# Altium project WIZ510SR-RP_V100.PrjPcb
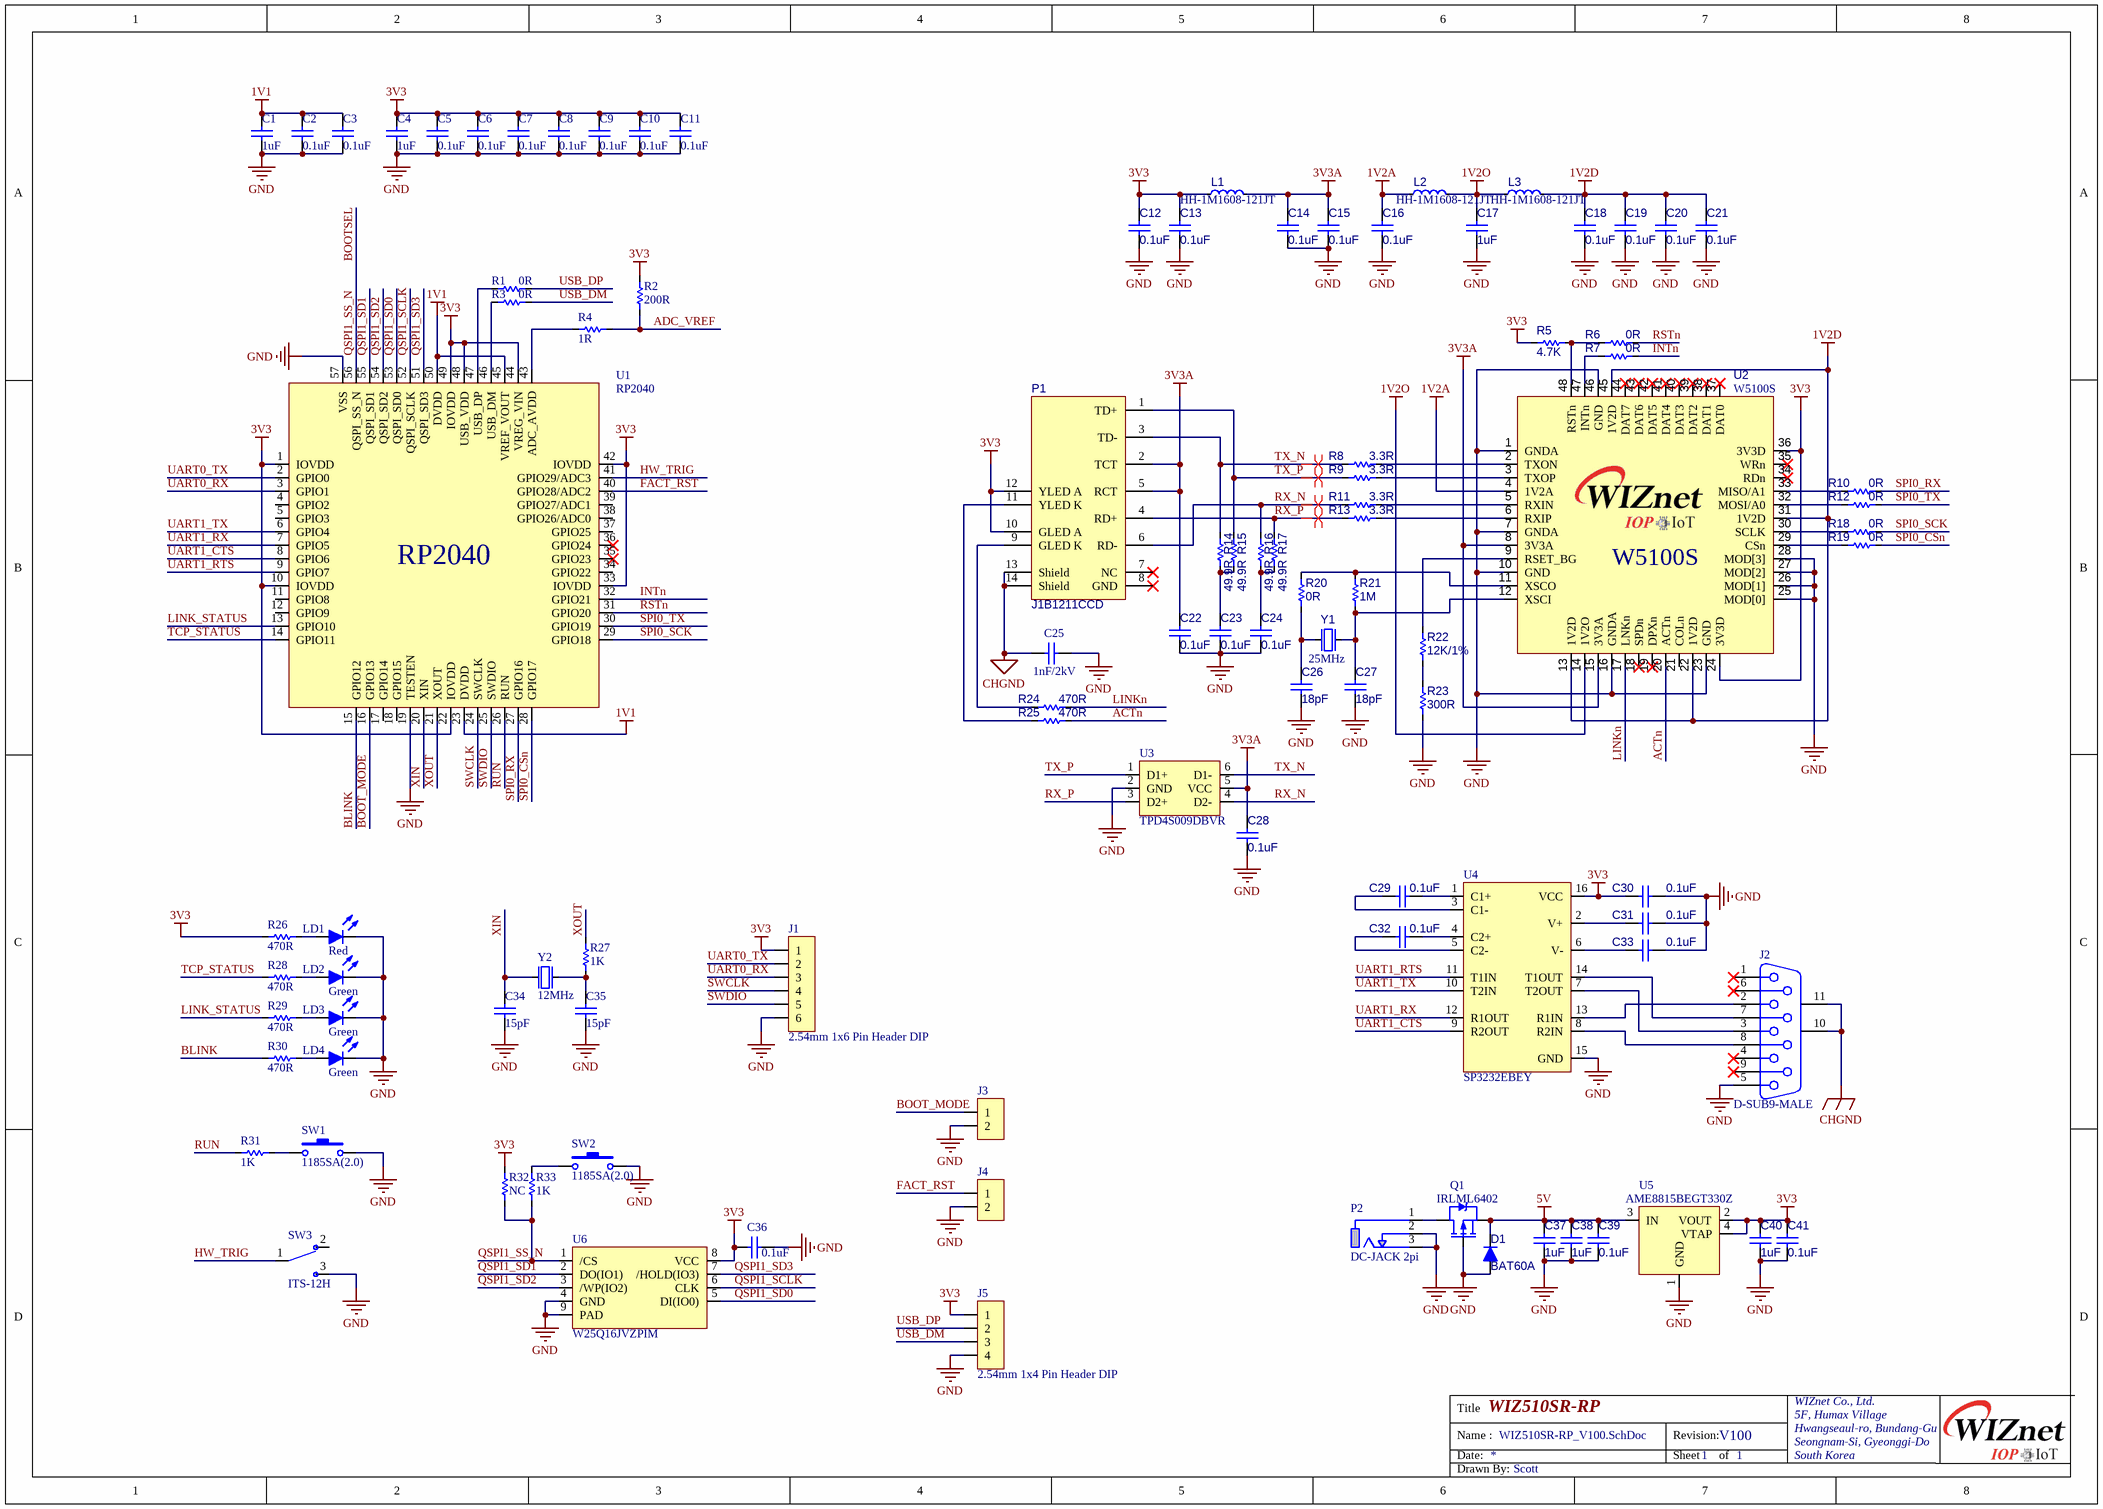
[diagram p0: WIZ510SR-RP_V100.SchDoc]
1 sheet, 101 parts. Net scope: global (net labels, ports and power ports of the same name join across sheets).
Board file: WIZ510SR-RP_V100.PcbDoc

## Sheet WIZ510SR-RP_V100.SchDoc: WIZ510SR-RP
size A3; DrawnBy: Scott; Organization: WIZnet Co., Ltd.; Address1: 5F, Humax Village; Address2: Hwangseaul-ro, Bundang-Gu; Address3: Seongnam-Si, Gyeonggi-Do; Address4: South Korea; Revision: V100; SheetNumber: 1; SheetTotal: 1

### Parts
C1  1uF  [CAP-0402]
C2  0.1uF  [CAP-0402]
C3  0.1uF  [CAP-0402]
C4  1uF  [CAP-0402]
C5  0.1uF  [CAP-0402]
C6  0.1uF  [CAP-0402]
C7  0.1uF  [CAP-0402]
C8  0.1uF  [CAP-0402]
C9  0.1uF  [CAP-0402]
C10  0.1uF  [CAP-0402]
C11  0.1uF  [CAP-0402]
C12  0.1uF  [CAP-0402]
C13  0.1uF  [CAP-0402]
C14  0.1uF  [CAP-0402]
C15  0.1uF  [CAP-0402]
C16  0.1uF  [CAP-0402]
C17  1uF  [CAP-0402]
C18  0.1uF  [CAP-0402]
C19  0.1uF  [CAP-0402]
C20  0.1uF  [CAP-0402]
C21  0.1uF  [CAP-0402]
C22  0.1uF  [CAP-0402]
C23  0.1uF  [CAP-0402]
C24  0.1uF  [CAP-0402]
C25  1nF/2kV  [CAP-1808]
C26  18pF  [CAP-0402]
C27  18pF  [CAP-0402]
C28  0.1uF  [CAP-0402]
C29  0.1uF  [CAP-0402]
C30  0.1uF  [CAP-0402]
C31  0.1uF  [CAP-0402]
C32  0.1uF  [CAP-0402]
C33  0.1uF  [CAP-0402]
C34  15pF  [CAP-0402]
C35  15pF  [CAP-0402]
C36  0.1uF  [CAP-0402]
C37  1uF  [CAP-0402]
C38  1uF  [CAP-0402]
C39  0.1uF  [CAP-0402]
C40  1uF  [CAP-0402]
C41  0.1uF  [CAP-0402]
D1  BAT60A  [SOD-323(1-C,2-A)]
J1  2.54mm 1x6 Pin Header DIP  [IDC-1X6]
J2  D-SUB9-MALE  [D-SUB9-MALE]
J3  2.54mm 1x2 Pin Header DIP  [IDC-1X2]  (value not drawn)
J4  2.54mm 1x2 Pin Header DIP  [IDC-1X2]  (value not drawn)
J5  2.54mm 1x4 Pin Header DIP  [IDC-1X4]
L1  HH-1M1608-121JT  [IND-0603]
L2  HH-1M1608-121JT  [IND-0603]
L3  HH-1M1608-121JT  [IND-0603]
LD1  Red  [LED-0603-RED]
LD2  Green  [LED-0603-green]
LD3  Green  [LED-0603-green]
LD4  Green  [LED-0603-green]
P1  J1B1211CCD  [RJ45-J1B1211CCD]
P2  DC-JACK 2pi  [DC-JACK 2pi]
Q1  IRLML6402  [SOT-23-3L]
R1  0R  [RES-0402]
R2  200R  [RES-0402]
R3  0R  [RES-0402]
R4  1R  [RES-0402]
R5  4.7K  [RES-0402]
R6  0R  [RES-0402]
R7  0R  [RES-0402]
R8  3.3R  [RES-0402]
R9  3.3R  [RES-0402]
R10  0R  [RES-0402]
R11  3.3R  [RES-0402]
R12  0R  [RES-0402]
R13  3.3R  [RES-0402]
R14  49.9R  [RES-0402]
R15  49.9R  [RES-0402]
R16  49.9R  [RES-0402]
R17  49.9R  [RES-0402]
R18  0R  [RES-0402]
R19  0R  [RES-0402]
R20  0R  [RES-0402]
R21  1M  [RES-0402]
R22  12K/1%  [RES-0402]
R23  300R  [RES-0402]
R24  470R  [RES-0402]
R25  470R  [RES-0402]
R26  470R  [RES-0402]
R27  1K  [RES-0402]
R28  470R  [RES-0402]
R29  470R  [RES-0402]
R30  470R  [RES-0402]
R31  1K  [RES-0402]
R32  NC  [RES-0402]
R33  1K  [RES-0402]
SW1  1185SA(2.0)  [ST-1185S]
SW2  1185SA(2.0)  [ST-1185S]
SW3  ITS-12H  [ITS-12H]
U1  RP2040  [RP2040_QFN56(0.4/7X7)]
U2  W5100S  [LQFP48(0.5/9.0)]
U3  TPD4S009DBVR  [SOT-23-6L]
U4  SP3232EBEY  [TSSOP16(0.65/6.4)]
U5  AME8815BEGT330Z  [SOT-223]
U6  W25Q16JVZPIM  [WSON8(6X5_1.27)]
Y1  25MHz  [OSC-82J0626]
Y2  12MHz  [OSC-TZ1067B]

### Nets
1V1: C1.2 C2.2 C3.2 U1.23(DVDD) U1.45(VREF_VOUT) U1.50(DVDD)
1V2A: C16.2 L2.1 U2.4(1V2A)
1V2D: C18.2 C19.2 C20.2 C21.2 L3.2 U2.13(1V2D) U2.22(1V2D) U2.31(1V2D) U2.45(1V2D)
1V2O: C17.2 L2.2 L3.1 U2.14(1V2O)
3V3: C4.2 C5.2 C6.2 C7.2 C8.2 C9.2 C10.2 C11.2 C12.2 C13.2 C30.2 C36.2 C40.2 C41.2 J1.1 J5.1 L1.1 P1.10(GLED_A) P1.12(YLED_A) R2.1 R5.1 R26.2 R32.2 U1.1(IOVDD) U1.10(IOVDD) U1.22(IOVDD) U1.33(IOVDD) U1.42(IOVDD) U1.44(VREG_VIN) U1.48(USB_VDD) U1.49(IOVDD) U2.24(3V3D) U2.36(3V3D) U4.16(VCC) U5.2(VOUT) U5.4(VTAP) U6.8(VCC)
3V3A: C14.2 C15.2 C22.2 C28.2 L1.2 P1.2(TCT) P1.5(RCT) U2.8(3V3A) U2.15(3V3A) U3.5(VCC)
5V: C37.2 C38.2 C39.2 D1.1(K) Q1.2(S) U5.3(IN)
CHGND: C25.2 J2.10(MH1) J2.11(MH2) P1.13(Shield) P1.14(Shield)
GND: C1.1 C2.1 C3.1 C4.1 C5.1 C6.1 C7.1 C8.1 C9.1 C10.1 C11.1 C12.1 C13.1 C14.1 C15.1 C16.1 C17.1 C18.1 C19.1 C20.1 C21.1 C22.1 C23.1 C24.1 C25.1 C26.1 C27.1 C28.1 C30.1 C31.1 C33.1 C34.2 C35.2 C36.1 C37.1 C38.1 C39.1 C40.1 C41.1 D1.2(A) J1.6 J2.5 J3.2 J4.2 J5.4 LD1.2(K) LD2.2(K) LD3.2(K) LD4.2(K) P2.2(GND) P2.3(GND) Q1.1(G) R23.2 SW1.2 SW2.2 SW3.3 U1.19(TESTEN) U1.57(VSS) U2.1(GNDA) U2.7(GNDA) U2.10(GND) U2.16(GNDA) U2.23(GND) U2.25(MOD[0]) U2.26(MOD[1]) U2.27(MOD[2]) U2.28(MOD[3]) U2.46(GND) U3.2(GND) U4.15(GND) U5.1(GND) U6.4(GND) U6.9(PAD) Y1.2(GND) Y1.4(GND) Y2.2 Y2.4
ACTn: R25.2 U2.20(ACTn)
ADC_VREF: R2.2 R4.2
BLINK: R30.2 U1.15(GPIO12)
BOOT_MODE: J3.1 U1.16(GPIO13)
BOOTSEL: R32.1 R33.1 U1.56(QSPI_SS_N) U6.1(/CS)  [also labelled QSPI1_SS_N]
FACT_RST: J4.1 U1.40(GPIO28/ADC2)
HW_TRIG: SW3.1 U1.41(GPIO29/ADC3)
INTn: R7.2 U1.32(GPIO21)
LINK_STATUS: R29.2 U1.13(GPIO10)
LINKn: R24.2 U2.17(LNKn)
QSPI1_SCLK: U1.52(QSPI_SCLK) U6.6(CLK)
QSPI1_SD0: U1.53(QSPI_SD0) U6.5(DI(IO0))
QSPI1_SD1: U1.55(QSPI_SD1) U6.2(DO(IO1))
QSPI1_SD2: U1.54(QSPI_SD2) U6.3(/WP(IO2))
QSPI1_SD3: U1.51(QSPI_SD3) U6.7(/HOLD(IO3))
RSTn: R6.2 U1.31(GPIO20)
RUN: R31.2 U1.26(RUN)
RX_N: P1.6(RD-) R11.1 R16.2 U3.4(D2-)
RX_P: P1.4(RD+) R13.1 R17.2 U3.3(D2+)
SPI0_CSn: R19.2 U1.28(GPIO17)
SPI0_RX: R10.2 U1.27(GPIO16)
SPI0_SCK: R18.2 U1.29(GPIO18)
SPI0_TX: R12.2 U1.30(GPIO19)
SWCLK: J1.4 U1.24(SWCLK)
SWDIO: J1.5 U1.25(SWDIO)
TCP_STATUS: R28.2 U1.14(GPIO11)
TX_N: P1.3(TD-) R8.1 R14.2 U3.6(D1-)
TX_P: P1.1(TD+) R9.1 R15.2 U3.1(D1+)
UART0_RX: J1.3 U1.3(GPIO1)
UART0_TX: J1.2 U1.2(GPIO0)
UART1_CTS: U1.8(GPIO6) U4.9(R2OUT)
UART1_RTS: U1.9(GPIO7) U4.11(T1IN)
UART1_RX: U1.7(GPIO5) U4.12(R1OUT)
UART1_TX: U1.6(GPIO4) U4.10(T2IN)
USB_DM: J5.3 R3.1
USB_DP: J5.2 R1.1
XIN: C34.1 U1.20(XIN) Y2.1(inp)
XOUT: R27.2 U1.21(XOUT)
NetC23_2: C23.2 R14.1 R15.1
NetC24_2: C24.2 R16.1 R17.1
NetC26_2: C26.2 R20.1 Y1.1(inp)
NetC27_2: C27.2 R21.1 U2.12(XSCI) Y1.3(out)
NetC29_1: C29.1 U4.1(C1+)
NetC29_2: C29.2 U4.3(C1-)
NetC31_2: C31.2 U4.2(V+)
NetC32_1: C32.1 U4.4(C2+)
NetC32_2: C32.2 U4.5(C2-)
NetC33_2: C33.2 U4.6(V-)
NetC35_1: C35.1 R27.1 Y2.3(out)
NetJ2_2: J2.2 U4.13(R1IN)
NetJ2_3: J2.3 U4.7(T2OUT)
NetJ2_7: J2.7 U4.14(T1OUT)
NetJ2_8: J2.8 U4.8(R2IN)
NetLD1_1: LD1.1(A) R26.1
NetLD2_1: LD2.1(A) R28.1
NetLD3_1: LD3.1(A) R29.1
NetLD4_1: LD4.1(A) R30.1
NetP1_9: P1.9(GLED_K) R24.1
NetP1_11: P1.11(YLED_K) R25.1
NetP2_1: P2.1(VCC) Q1.3(D)
NetR1_2: R1.2 U1.47(USB_DP)
NetR3_2: R3.2 U1.46(USB_DM)
NetR4_1: R4.1 U1.43(ADC_AVDD)
NetR5_2: R5.2 R6.1 U2.48(RSTn)
NetR7_1: R7.1 U2.47(INTn)
NetR8_2: R8.2 U2.2(TXON)
NetR9_2: R9.2 U2.3(TXOP)
NetR10_1: R10.1 U2.33(MISO/A1)
NetR11_2: R11.2 U2.5(RXIN)
NetR12_1: R12.1 U2.32(MOSI/A0)
NetR13_2: R13.2 U2.6(RXIP)
NetR18_1: R18.1 U2.30(SCLK)
NetR19_1: R19.1 U2.29(CSn)
NetR20_2: R20.2 R21.2 U2.11(XSCO)
NetR22_1: R22.1 U2.9(RSET_BG)
NetR22_2: R22.2 R23.1
NetR31_1: R31.1 SW1.1
NetR33_2: R33.2 SW2.1

Not connected (* = marked no-connect by the designer): J2 1* 4* 6* 9*; P1 7(NC)* 8(GND)*; SW3 2; U1 4(GPIO2) 5(GPIO3) 11(GPIO8) 12(GPIO9) 17(GPIO14) 18(GPIO15) 34(GPIO22) 35(GPIO23)* 36(GPIO24)* 37(GPIO25) 38(GPIO26/ADC0) 39(GPIO27/ADC1); U2 18(SPDn)* 19(DPXn)* 21(COLn) 34(RDn)* 35(WRn)* 37(DAT0)* 38(DAT1)* 39(DAT2)* 40(DAT3)* 41(DAT4)* 42(DAT5)* 43(DAT6)* 44(DAT7)*

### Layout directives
differential pair: RX_N, RX_P, TX_N, TX_P

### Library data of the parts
C1-C24 C26-C41 = CAP-0402: Ceramic CAP 0402(1005)
C25 = CAP-1808: Ceramic CAP 1808(4520)
D1 = DIODE-BAT60A: Silicon Schottky Diode
J2 = D-SUB9-MALE: D-SUB-9, MALE,  Right Angle; PackageDocument: O; Positions: 9; Gender: Receptacle
L1-L3 = IND-0603: Inductor 0603(1608)
LD1-LD4 = LED-0603
Q1 = Q-IRLML6402: HEXFET Power MOSFET
R1-R33 = RES-0402
SW1 SW2 = ITS-1107(SMD): TACT Switch (SMD)
SW3 = ITS-12H: Slide Switch
U1 = RP2040: Raspverry Pi, Dual ARM Cortex-M0+ @ 133MHz
U2 = W5100S: WIZnet Hardwired TCP/IP Chip
U3 = TPD4S009DBKR: 4-Channel ESD Solution for High-Speed Differential Interface
U4 = SP3232EBEY: True +3.0V to +5.5V RS-232 Transceivers
U5 = AME8815BEGT330Z: 1.5A CMOS LDO
U6 = W25Q16JVZPIM: 3V 16M-BIT / SERIAL FLASH MEMORY WITH / DUAL/QUAD SPI, QPI & DTR
Y1 = OSC-82J0626-25MHz: X-tal 25MHz,3.2x2.5 SMD, CL=18pF
Y2 = OSC-TZ1067B-12MHz: X-tal 12MHz,3.2x2.5 SMD, CL=20pF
